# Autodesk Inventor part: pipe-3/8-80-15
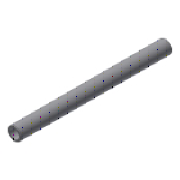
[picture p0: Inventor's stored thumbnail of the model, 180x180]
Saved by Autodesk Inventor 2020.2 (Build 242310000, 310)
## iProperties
Manager: www.cadconsulting.pl
Company: Fabian Stasiak CAD Consulting
Created: 2014-08
Part Number: pipe-3/8-80-15
Material: Ogólny
Document SubType Name: Modeling
Designer: F.Stasiak
Manufacturer: Standard
Standards Organization: Custom
Language: pl-PL
Size Designation: 3/8-80-15
Categories: <MemberInstance><Categories><Category DisplayName="Rury cienko- i grubościenne" InternalName="4347fa0f-2144-441d-94cd-e3e15c92b736" Mnemonic="TUBEANDPIPE"><Cate
Density: 1 g/cm^3
Appearance: Domyślna
Catalog Web Link: www.expertbooks.pl
IsCustomPart: 0
Author: F.Stasiak
Subject: Zbiór ćwiczeń. Autodesk Inventor 2020. Kurs Professional
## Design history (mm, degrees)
node "Punkt konstrukcyjny1"
node "Punkt konstrukcyjny2"
node "Oś konstrukcyjna1"
node "Oś konstrukcyjna2"
body "Solid1"
sketch "Sketch1"
  geometry: C1 r 8.573 at (0, 0); C2 r 5.372 at (0, 0)
  constraints: 2 centre point, 1 coincident
  dimensions: "d0" = 10.7442 diameter of C2 (= ID); "d1" = 17.145 diameter of C1 (= OD)
extrude "Wyciągnięcie proste1" new body sketch "Sketch1" distance "d2" = 381 (= PL); taper "d3" = 0 deg
chamfer "Faza1" distance "d4" = 1.0668 (= t); stored, may be unused: second distance "d5" = 3.175, angle "d6" = 45 deg
other parameters: "OD" = 17.145 [user parameter; used in 2 equation terms], "ID" = 10.7442 [user parameter; used in 2 equation terms], "PL" = 381 [user parameter; used in 1 equation term], "t" = 1.0668 (= -0.166667 x ID + 0.166667 x OD) [user parameter; used in 1 equation term]
